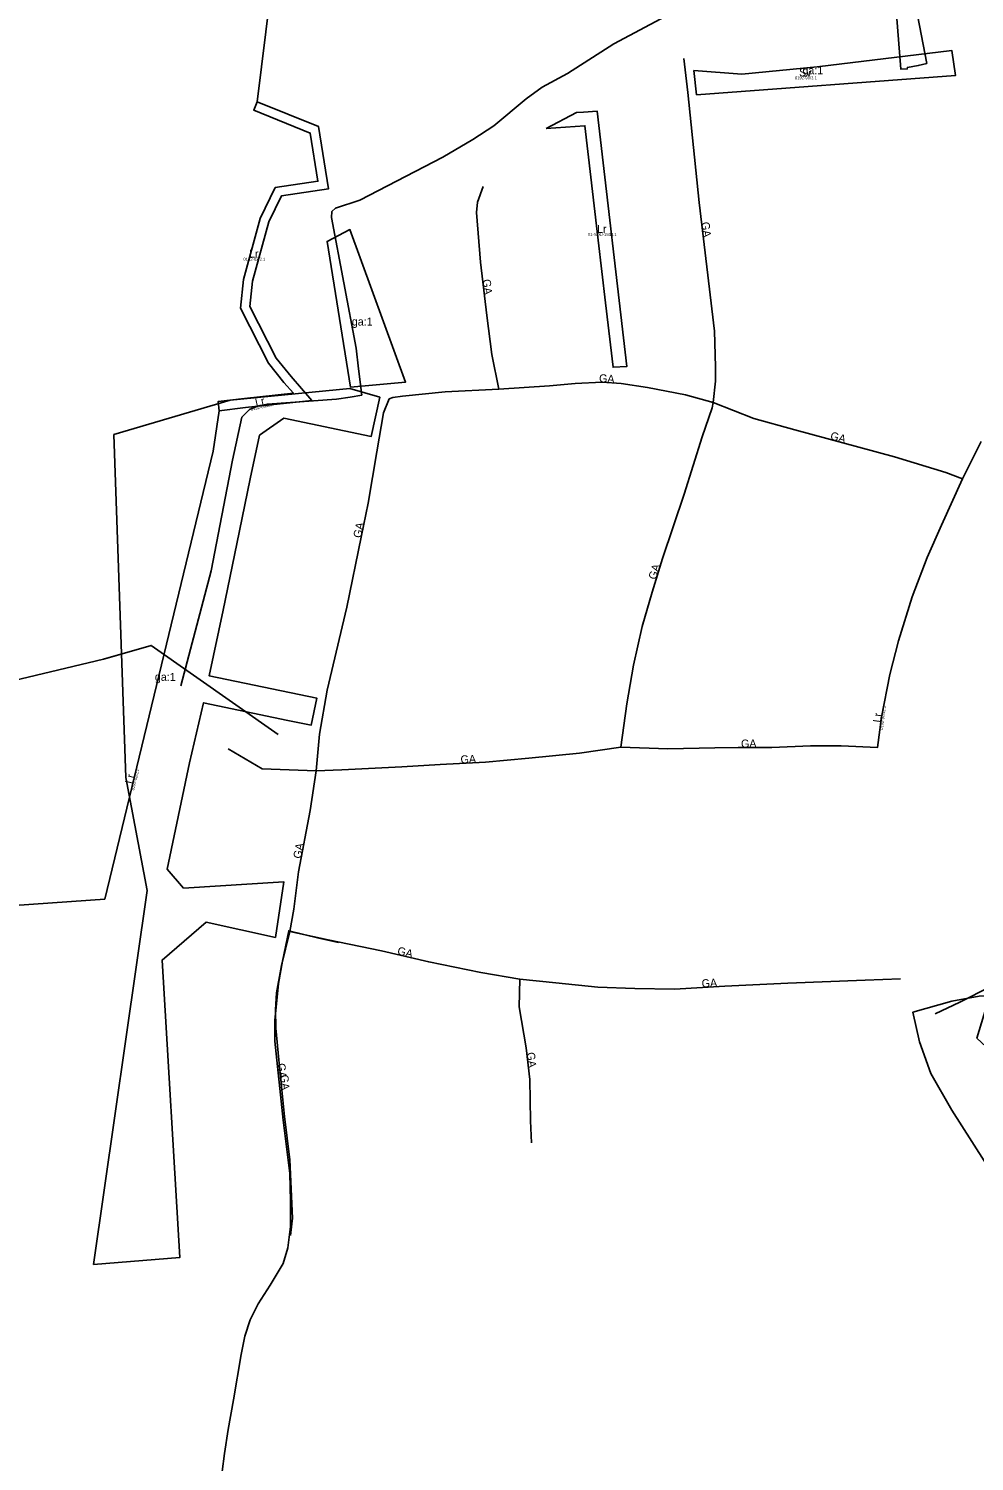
# Model space of a CAD drawing. Extents: x 140791 to 143631, y 6542790 to 6549933.
# Drawn here: x 142121 to 142535, y 6548024 to 6548650 of the extents above; entities that cross this region are included whole.
import ezdxf

# ---------------------------------------------------------------- set-up
doc = ezdxf.new("R2010")
doc.units = 0
for name, color, linetype in [('RATT Aktbeteckning för ledningsrätt', 7, 'Continuous'), ('RATT Aktbeteckning för servitut', 7, 'Continuous'), ('RATT Beteckning för gemensammhetsanläggning', 7, 'Continuous'), ('RATT Beteckning för ledningsrätt', 7, 'Continuous'), ('RATT Beteckning för servitut', 7, 'Continuous'), ('RATT Gemensamhetsanläggning', 7, 'Continuous'), ('RATT Gemensamhetsanläggningsgräns', 7, 'Continuous'), ('RATT Ledningsrätt', 7, 'Continuous'), ('RATT Ledningsrättsgräns', 7, 'Continuous')]:
    doc.layers.add(name, color=color, linetype=linetype)

msp = doc.modelspace()

# ---------------------------------------------------------------- linework, layer by layer
at = {"layer": 'RATT Gemensamhetsanläggning'}
for points in [[(142407.52, 6548636.94), (142409.29, 6548622.07), (142414.21, 6548573.98), (142420.95, 6548517.76), (142421.38, 6548502.2), (142421.35, 6548495.9), (142420.36, 6548486.64)], [(142326.64, 6548492.47), (142323.55, 6548507.52), (142321.41, 6548524.6), (142318.56, 6548548), (142316.84, 6548569.61), (142317.26, 6548574.14), (142319.81, 6548580.96)], [(142420.36, 6548486.64), (142408.27, 6548489.97), (142391.64, 6548493.09), (142380.1, 6548494.89), (142371.76, 6548495.42), (142360.01, 6548494.88), (142348.83, 6548493.89), (142326.64, 6548492.47)], [(142326.64, 6548492.47), (142303.14, 6548491.25), (142284.45, 6548489.29), (142280.19, 6548488.83), (142278.7, 6548488.14), (142276.18, 6548482.05), (142273.19, 6548464.98), (142269.46, 6548442.5), (142266.39, 6548427.63), (142260.08, 6548397.02), (142251.56, 6548360.75), (142248.22, 6548341.48), (142246.73, 6548325.54)], [(142420.36, 6548486.64), (142419.98, 6548484.2), (142415.51, 6548471.58), (142407.75, 6548446.43), (142398.14, 6548418.4), (142393.75, 6548403.71), (142389.36, 6548388.59), (142385.5, 6548371.69), (142382.66, 6548354.76), (142379.92, 6548335.92)], [(142529.38, 6548453.18), (142522.13, 6548456.03), (142499.74, 6548462.83), (142484.02, 6548467.1), (142456.08, 6548474.65), (142438.18, 6548479.57), (142420.36, 6548486.64)], [(142246.73, 6548325.54), (142257.89, 6548325.95), (142284.18, 6548327.25), (142300.93, 6548328.23), (142320.76, 6548329.27), (142339.73, 6548331.07), (142361.94, 6548333.21), (142379.92, 6548335.92)], [(142379.92, 6548335.92), (142400.58, 6548335.18), (142421.12, 6548335.61), (142446.06, 6548335.77), (142462.95, 6548336.46), (142476.3, 6548336.51), (142492.27, 6548335.76)], [(142517.51, 6548219.31), (142528.21, 6548224.43), (142555.44, 6548238.01), (142575.5, 6548246.96), (142597.98, 6548258.63), (142618.47, 6548272.55), (142635.82, 6548284.37), (142647.64, 6548292.24), (142658.03, 6548296.77), (142675.82, 6548303.3), (142698.92, 6548310.99), (142714.57, 6548314.64), (142730.68, 6548319.16), (142756.21, 6548324.58), (142769.32, 6548326.54), (142779.74, 6548326.82)], [(142246.73, 6548325.54), (142244.03, 6548308.17), (142239, 6548281.33), (142236.92, 6548264.96), (142235.17, 6548255.19)], [(142205.55, 6548019.09), (142206.62, 6548027.05), (142208.23, 6548037.49), (142210.5, 6548050.52), (142213.91, 6548070.32), (142215.52, 6548078.25), (142217.78, 6548085.41), (142221.28, 6548092.48), (142226.61, 6548100.59), (142232.21, 6548110.03), (142234.38, 6548116.92), (142235.55, 6548126.25), (142235.47, 6548137.55), (142235.16, 6548149.45), (142232.22, 6548172.75), (142228.68, 6548207.28), (142228.65, 6548216.43), (142229.37, 6548223.61), (142230.19, 6548232.54), (142231.96, 6548242.22), (142234.71, 6548255.62), (142247.81, 6548252.35), (142256.5, 6548250.44)], [(142235.17, 6548255.19), (142231.51, 6548240.34), (142229.41, 6548228.37), (142228.9, 6548221.05), (142229.11, 6548212.98), (142230.33, 6548199.16), (142232.84, 6548174.3), (142235.23, 6548155.46), (142236.39, 6548129.91), (142235.44, 6548122.31)], [(142335.78, 6548234.39), (142318.7, 6548237.38), (142295.95, 6548241.99), (142275.26, 6548246.85), (142251.93, 6548251.63), (142235.17, 6548255.19)], [(142340.84, 6548162.87), (142340.44, 6548172.51), (142340.23, 6548190.56), (142338.57, 6548204.39), (142335.57, 6548222.37), (142335.78, 6548234.39)], [(142502.26, 6548234.57), (142486.84, 6548233.99), (142453.06, 6548232.62), (142425.45, 6548231.36), (142403.42, 6548230.09), (142386.11, 6548230.3), (142369.85, 6548230.91), (142351.57, 6548232.76), (142335.78, 6548234.39)]]:
    msp.add_lwpolyline(points, dxfattribs=at)
at = {"layer": 'RATT Gemensamhetsanläggningsgräns'}
for points in [[(142413.11, 6548621.14), (142526.35, 6548629.53), (142524.78, 6548640.48), (142465.81, 6548633.39), (142432.88, 6548630.08), (142411.91, 6548631.7), (142413.11, 6548621.14)], [(142261.74, 6548493.27), (142285.85, 6548495.51), (142261.45, 6548562.17), (142251.5, 6548557.04), (142261.74, 6548493.27)], [(142191.26, 6548328.97), (142197.48, 6548355.26), (142234.29, 6548347.59), (142244.56, 6548345.5), (142247, 6548357.25), (142199.96, 6548367), (142206.03, 6548395.71), (142211.97, 6548424.74), (142217.87, 6548453.13), (142221.92, 6548472.29), (142232.58, 6548479.67), (142270.77, 6548471.74), (142274.49, 6548488.85), (142261.48, 6548492.76), (142209.1, 6548487.62), (142158.26, 6548472.58), (142163.49, 6548322.6), (142172.85, 6548273.19), (142149.35, 6548109.67)], [(142149.35, 6548109.67), (142187.09, 6548112.77), (142179.29, 6548242.76), (142198.58, 6548259.29), (142228.9, 6548252.69), (142232.53, 6548277.02), (142188.71, 6548274.21), (142181.56, 6548282.48), (142191.26, 6548328.97)], [(142585.14, 6548152.59), (142579.15, 6548166.3), (142569.8, 6548176.96), (142535.76, 6548208.56), (142540.84, 6548225.42), (142599.71, 6548228.49), (142598.66, 6548235.14), (142651.5, 6548237.73), (142632.54, 6548276.83), (142618.36, 6548266.91), (142606.99, 6548259.73), (142591.59, 6548250.39), (142572.23, 6548239.97), (142543.14, 6548227.16), (142536.68, 6548226.98), (142524.78, 6548224.73), (142507.74, 6548219.96), (142510.6, 6548207.08), (142515.53, 6548193.13), (142524.74, 6548177.16), (142543.35, 6548148.18), (142585.14, 6548152.59)]]:
    msp.add_lwpolyline(points, dxfattribs=at)
at = {"layer": 'RATT Ledningsrätt'}
msp.add_line((142220.88, 6548618.1), (142234.08, 6548723.11), dxfattribs=at)
for points in [[(142399.6, 6548655.51), (142376.91, 6548643.48), (142356.65, 6548630.37), (142345.63, 6548624.46), (142338.54, 6548619.4), (142324.44, 6548607.53), (142315.21, 6548601.51), (142302.07, 6548593.82), (142265.81, 6548575.08), (142255.13, 6548571.52), (142253.59, 6548570.16), (142253.39, 6548567.53), (142264.16, 6548510.32), (142265.29, 6548501.27), (142266.66, 6548489.82), (142261.56, 6548488.86), (142255.63, 6548488.09), (142225.36, 6548485.91), (142221.02, 6548484.93), (142217.52, 6548483.48), (142214.25, 6548480.22), (142210.07, 6548461.33), (142200.74, 6548412.99), (142187.56, 6548362.68)], [(141587.21, 6548224.88), (141596.19, 6548229.34), (141831.7, 6548246.84), (142154.26, 6548269.4), (142201.62, 6548465.33), (142204.3, 6548482.98)], [(142208.23, 6548335.13), (142223.02, 6548326.39), (142246.73, 6548325.54), (142257.89, 6548325.95), (142284.18, 6548327.25), (142300.93, 6548328.23), (142320.76, 6548329.27), (142339.73, 6548331.07), (142361.94, 6548333.21), (142379.92, 6548335.92), (142400.58, 6548335.18), (142421.12, 6548335.61), (142431.34, 6548335.68), (142446.06, 6548335.77), (142462.95, 6548336.46), (142476.3, 6548336.51), (142492.27, 6548335.76), (142493.97, 6548349.05), (142497.58, 6548367.57), (142501.38, 6548382.42), (142507.36, 6548401.6), (142514.02, 6548418.86), (142520.29, 6548432.91), (142529.38, 6548453.18), (142537.63, 6548469.51)], [(141753.31, 6548320.76), (141787.82, 6548309.21), (141889.95, 6548311.37), (142153.72, 6548374.34), (142174.54, 6548380.37), (142230.06, 6548341.39)], [(141753.31, 6548320.76), (141787.82, 6548309.21), (141889.95, 6548311.37), (142153.72, 6548374.34), (142161.44, 6548376.57)]]:
    msp.add_lwpolyline(points, dxfattribs=at)
at = {"layer": 'RATT Ledningsrättsgräns'}
for points in [[(142509.03, 6548659.71), (142513.82, 6548634.85), (142510.09, 6548633.87), (142505.3, 6548633.08), (142505.28, 6548632.48), (142502.52, 6548632.3), (142500.58, 6548656.41)], [(142220.88, 6548618.1), (142219.38, 6548614.39), (142244.11, 6548604.42), (142247.49, 6548583.31), (142228.82, 6548580.54), (142222.23, 6548567.01), (142214.9, 6548540.32), (142213.62, 6548527.76), (142225.81, 6548503.75), (142232.63, 6548495.39), (142236.78, 6548490.59), (142215.35, 6548488.32), (142203.83, 6548486.95), (142204.3, 6548482.98), (142215.79, 6548484.35), (142244.81, 6548487.42), (142235.7, 6548497.96), (142229.18, 6548505.94), (142217.72, 6548528.53), (142218.84, 6548539.58), (142225.99, 6548565.59), (142231.49, 6548576.89), (142252.08, 6548579.95), (142247.7, 6548607.29), (142220.88, 6548618.1)], [(142347.28, 6548606.46), (142360.61, 6548613.33), (142363.6, 6548613.55), (142369.58, 6548613.99), (142382.61, 6548502.39), (142376.62, 6548501.96), (142373.34, 6548530.12), (142370.12, 6548557.63), (142366.91, 6548585.14), (142364.29, 6548607.59), (142347.28, 6548606.46)]]:
    msp.add_lwpolyline(points, dxfattribs=at)

# ---------------------------------------------------------------- texts
at = {"layer": 'RATT Aktbeteckning för ledningsrätt'}
for s, p in [('01-SOU-1934.1', (142365.57, 6548559.44)), ('0192-02/2.1', (142214.89, 6548548.6))]:
    msp.add_text(s, height=1.3, dxfattribs=at).set_placement(p)
for s, rotation, p in [('0192-05/8.1', 12.788, (142218.29, 6548482.97)), ('0192-92/42.1', 82.688, (142494.55, 6548343.36)), ('0192-02/2.1', 76.386, (142167.07, 6548316.86))]:
    msp.add_text(s, height=1.3, rotation=rotation, dxfattribs=at).set_placement(p)
at = {"layer": 'RATT Aktbeteckning för servitut'}
msp.add_text('0192-90/3.1', height=1.3, dxfattribs=at).set_placement((142456.12, 6548627.89))
at = {"layer": 'RATT Beteckning för gemensammhetsanläggning'}
for p in [(142459.4, 6548630.09), (142262.3, 6548520.23), (142176.16, 6548364.86)]:
    msp.add_text('ga:1', height=3.5, dxfattribs=at).set_placement(p)
for rotation, p in [(276.739, (142415.25, 6548565.34)), (276.739, (142319.51, 6548540.28)), (356.38, (142370.36, 6548495.51)), (344.921, (142471.34, 6548470.53)), (78.313, (142266.29, 6548427.13)), (73.156, (142395.28, 6548408.88)), (0.573, (142432.56, 6548335.67)), (2.865, (142309.95, 6548328.71)), (79.459, (142240.05, 6548286.92)), (346.639, (142281.97, 6548245.28)), (3.255, (142415.42, 6548230.79)), (276.739, (142338.84, 6548202.25)), (275.958, (142229.68, 6548197.47)), (275.593, (142231.01, 6548192.49))]:
    msp.add_text('GA', height=3.5, rotation=rotation, dxfattribs=at).set_placement(p)
at = {"layer": 'RATT Beteckning för ledningsrätt'}
for p in [(142369.56, 6548560.74), (142217.36, 6548549.9)]:
    msp.add_text('Lr', height=3.5, dxfattribs=at).set_placement(p)
for rotation, p in [(12.788, (142220.42, 6548484.79)), (82.688, (142493.64, 6548346.48)), (76.386, (142166.39, 6548319.56))]:
    msp.add_text('Lr', height=3.5, rotation=rotation, dxfattribs=at).set_placement(p)
at = {"layer": 'RATT Beteckning för servitut'}
msp.add_text('Sv', height=3.5, dxfattribs=at).set_placement((142457.97, 6548629.19))

doc.saveas('drawing.dxf')
